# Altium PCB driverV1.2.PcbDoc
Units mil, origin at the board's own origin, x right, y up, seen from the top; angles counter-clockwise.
Board outline 6000 x 4000 mil, 2 copper layers (Top Layer, Bottom Layer); 172 components, 108 nets, 481 pads, 590 vias.
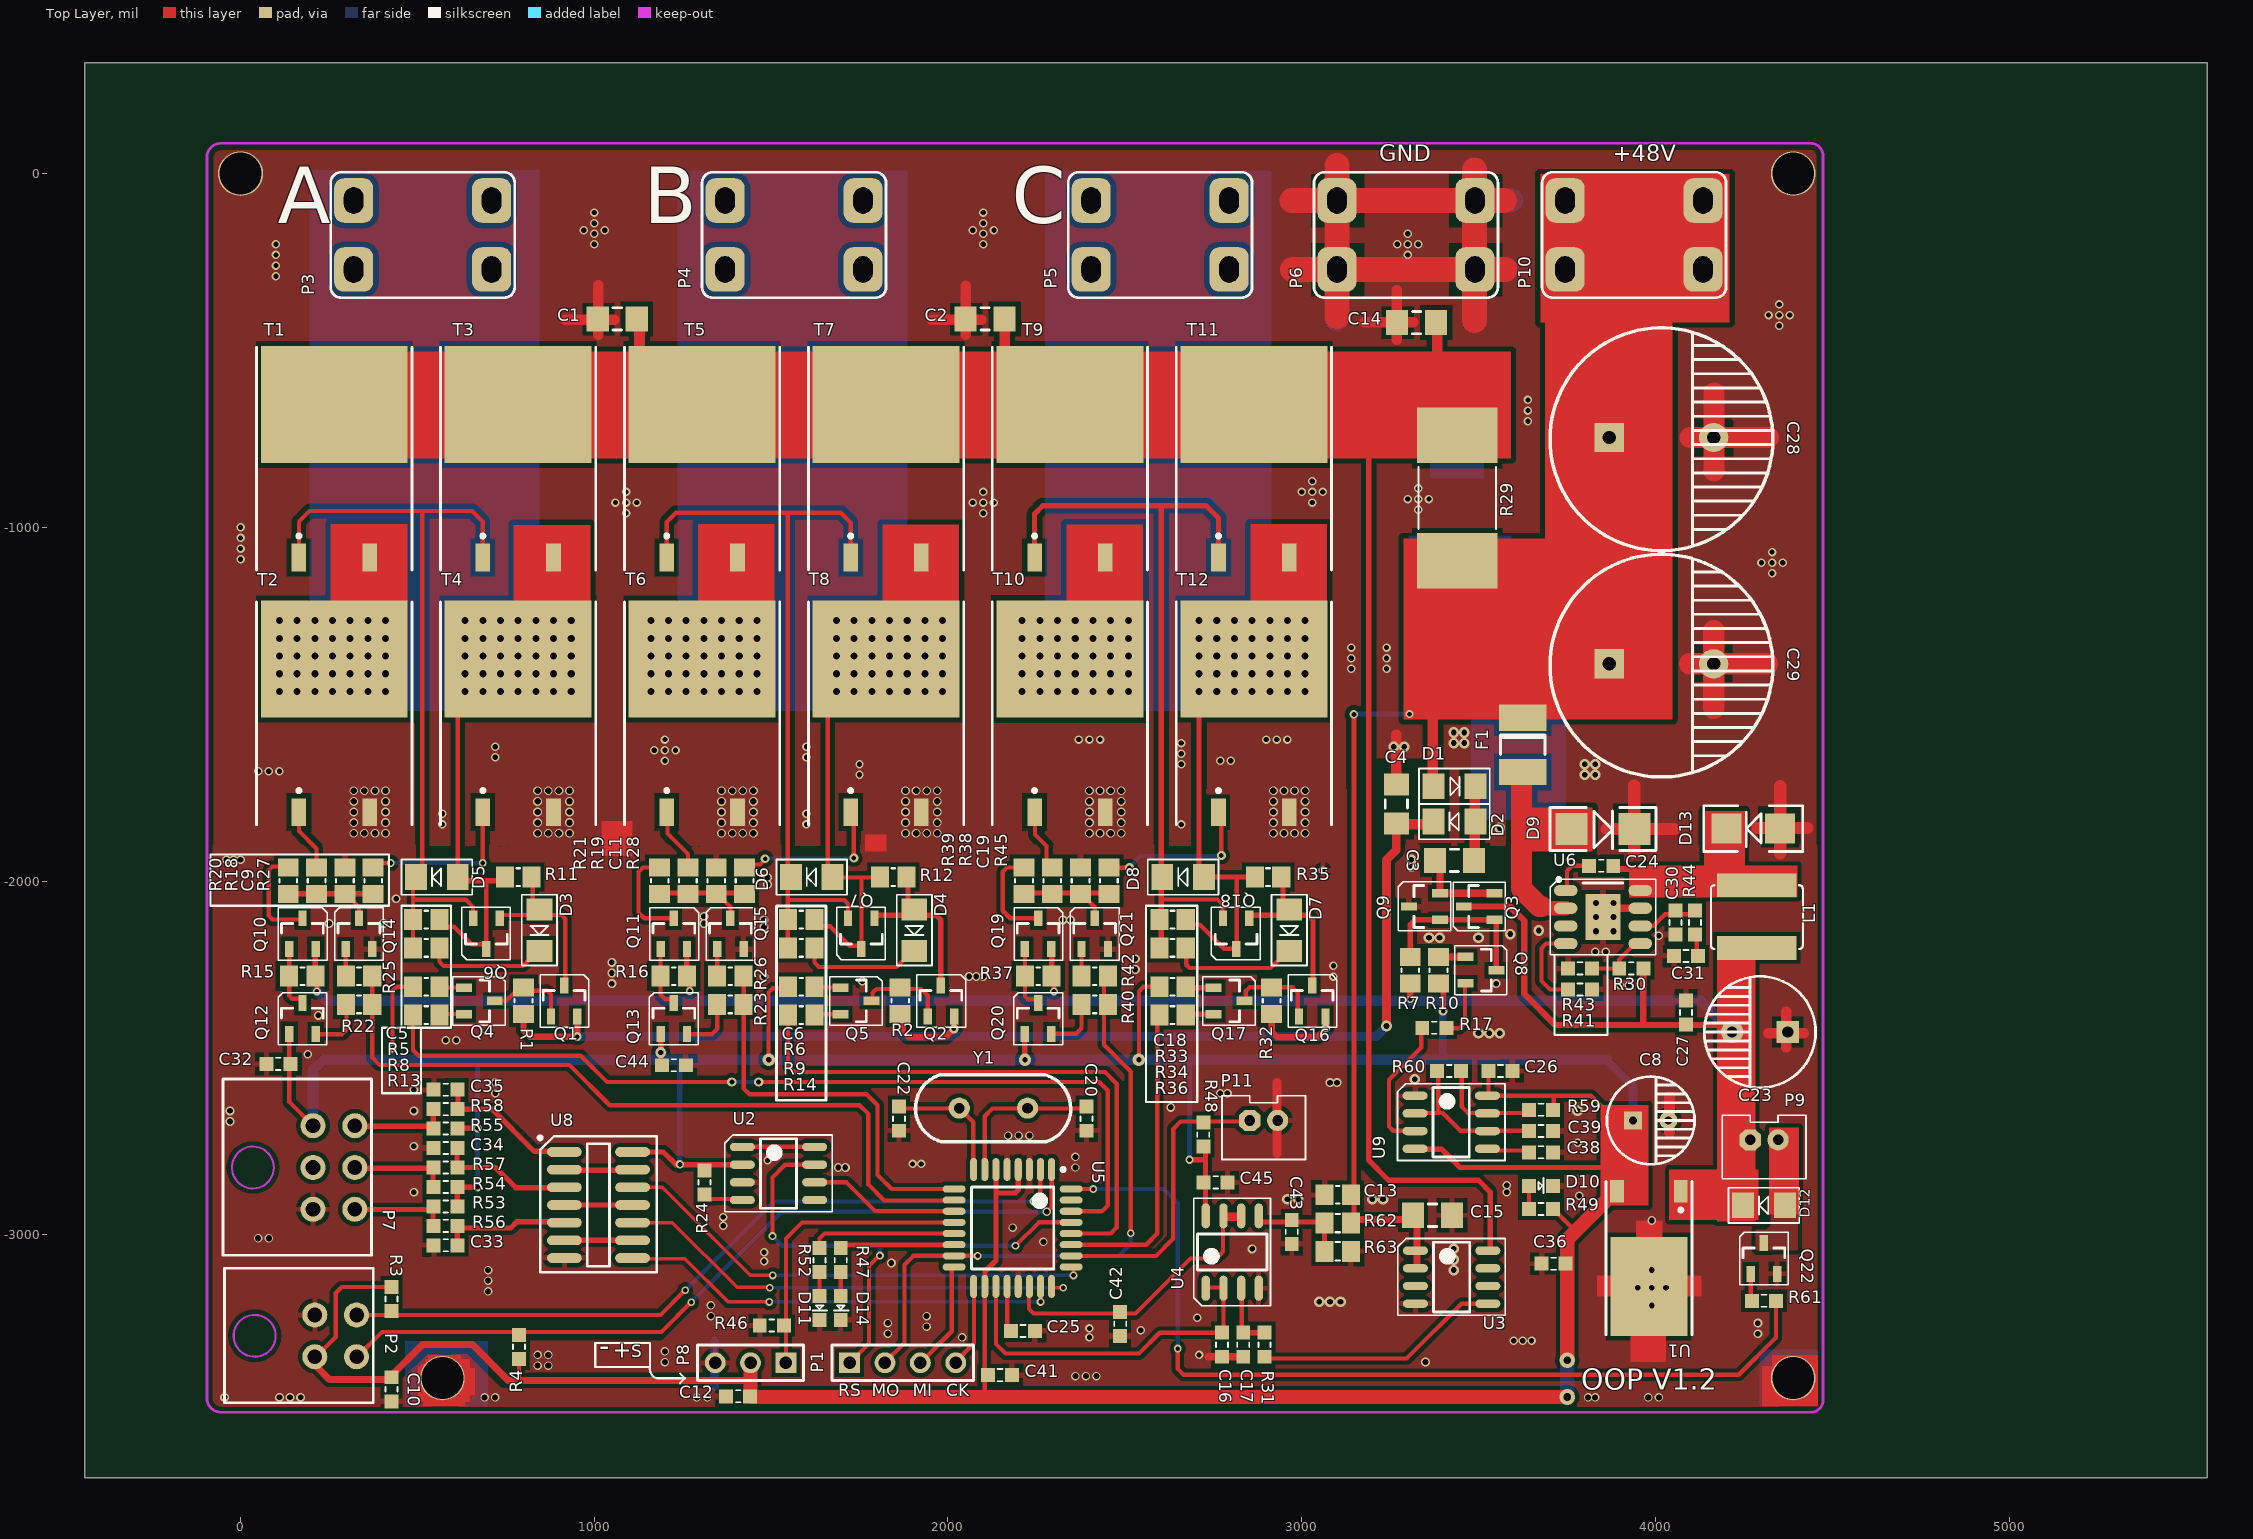
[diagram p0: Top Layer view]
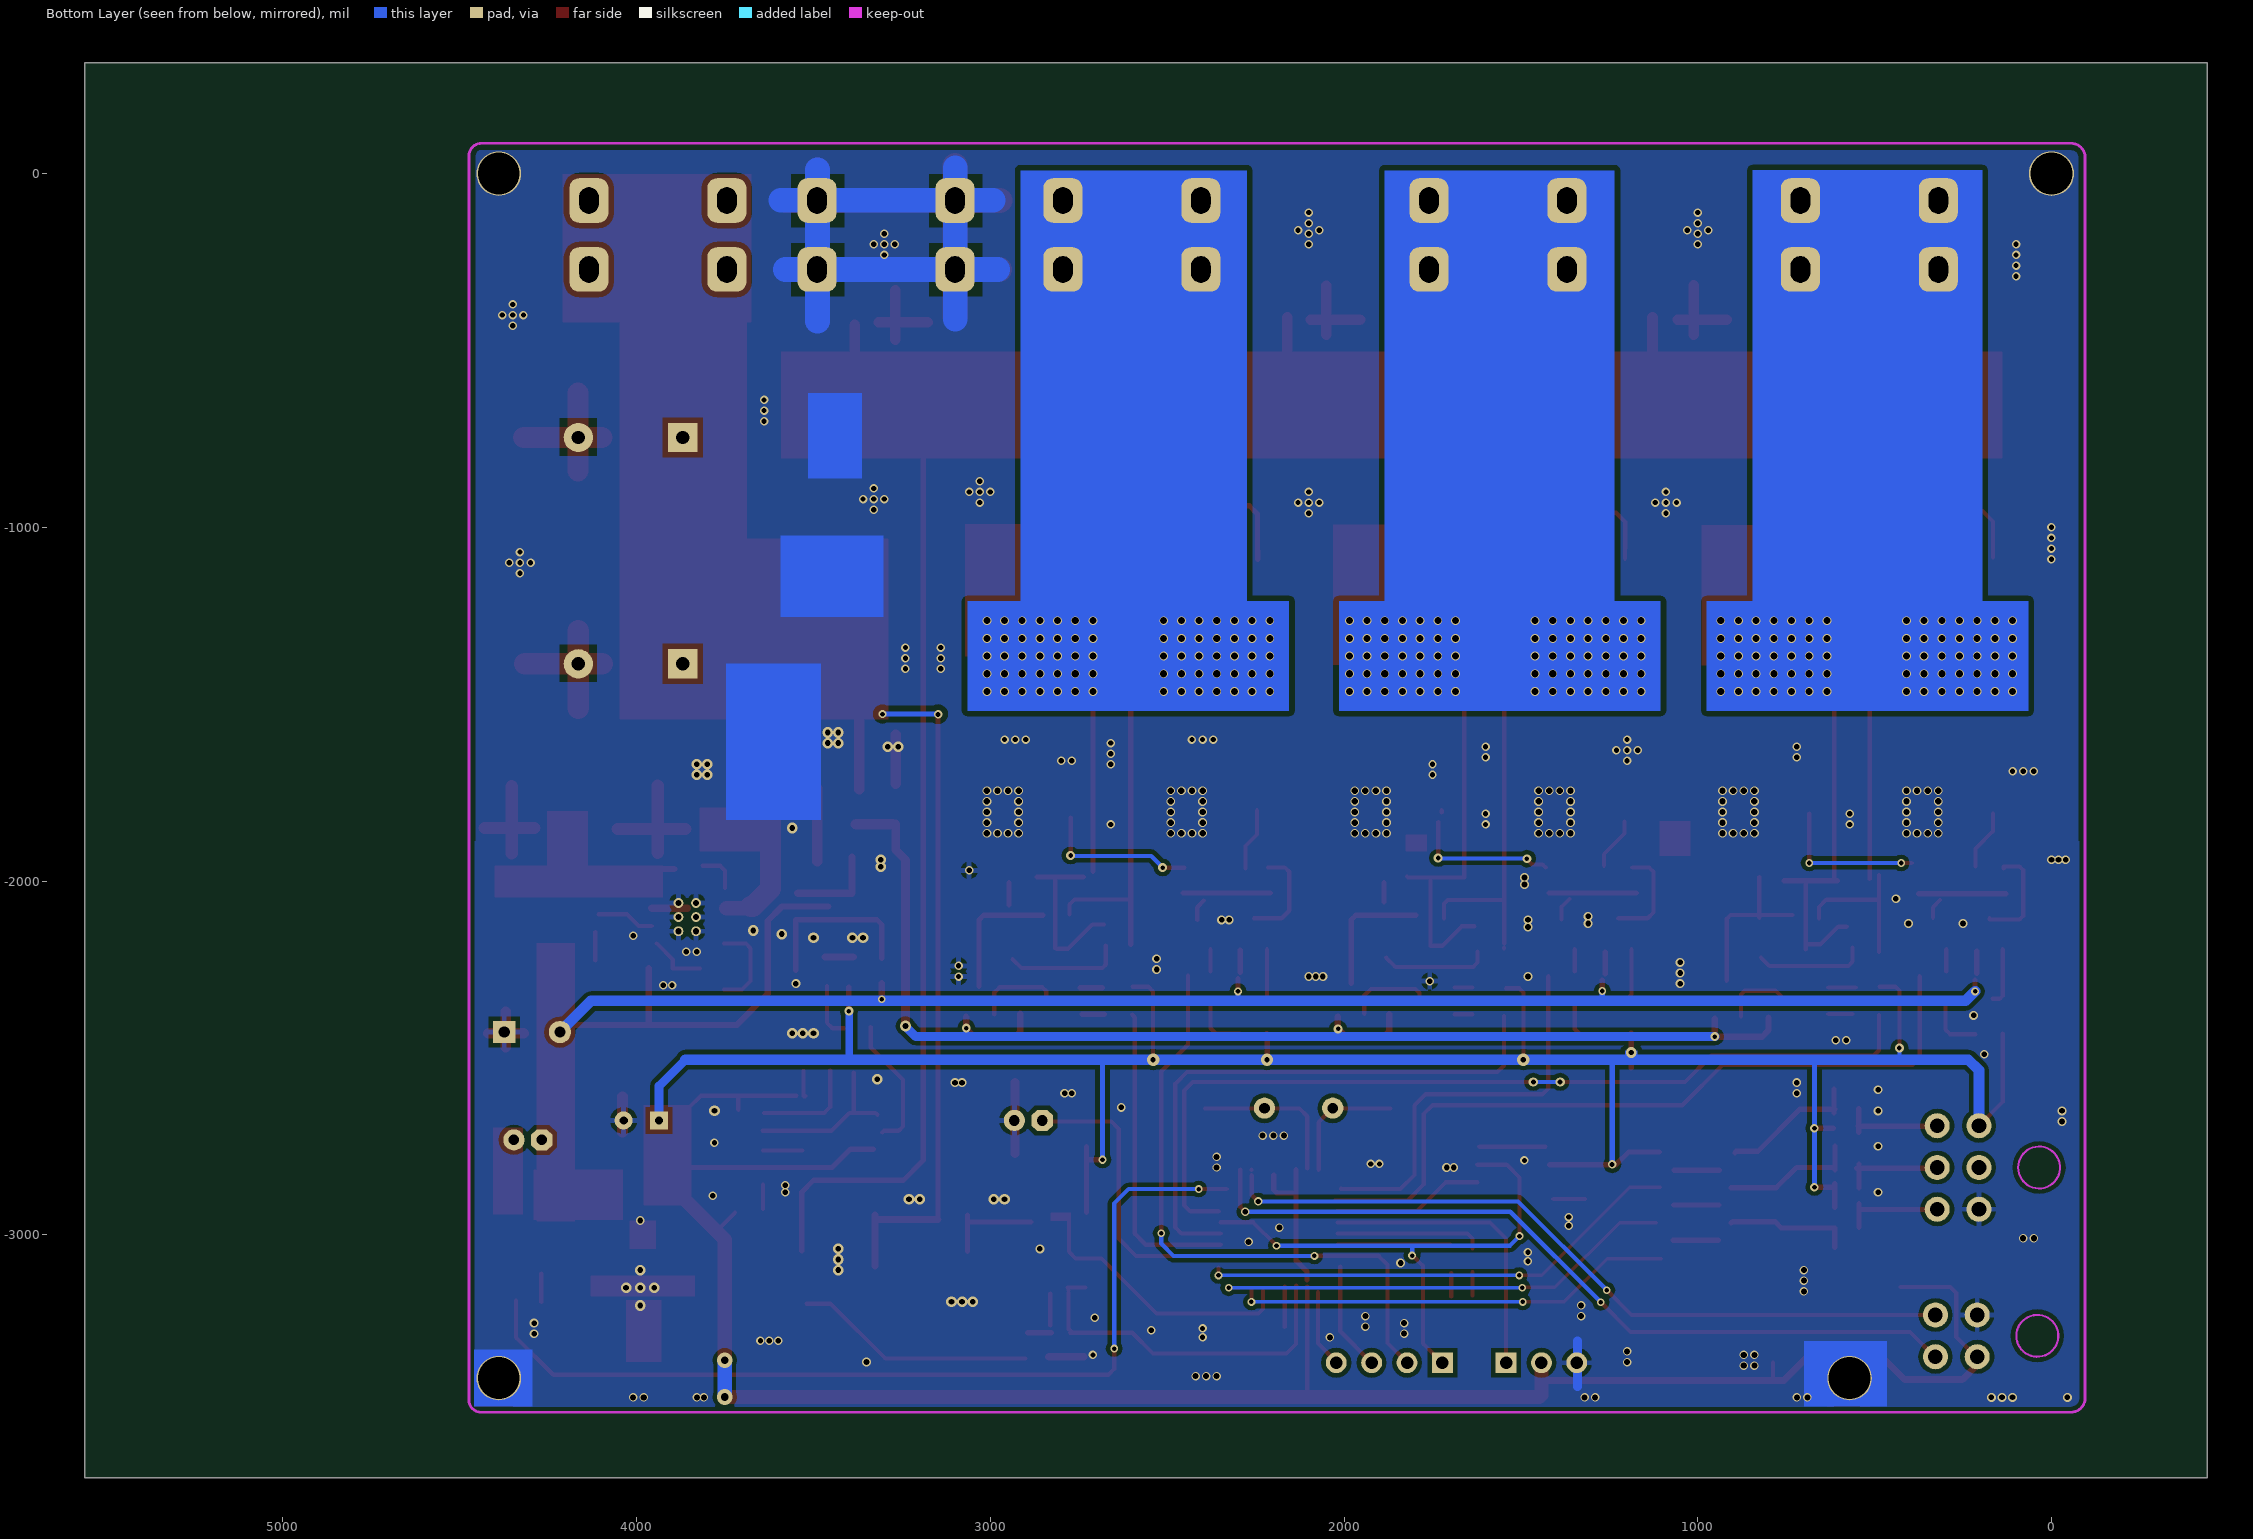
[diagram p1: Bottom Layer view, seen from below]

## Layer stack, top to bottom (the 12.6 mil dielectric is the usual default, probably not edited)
Top Solder: solder mask 0.4, Solder Resist, Dk 3.5
Top Layer: signal copper 1.4
Dielectric1: dielectric 12.6, FR-4, Dk 4.8
Bottom Layer: signal copper 1.4
Bottom Solder: solder mask 0.4, Solder Resist, Dk 3.5

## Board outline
-440,-3687 5560,-3687 5560,313 -440,313

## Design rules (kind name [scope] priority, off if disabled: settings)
Clearance [All] p1 off: gap=15
ComponentClearance [All] p1 off: gap=0 collisioncheckmode=3 verticalgap=0 showdistances=FALSE
FabricationTestPointUsage TestPointUsage [All] p1: valid=0 allowmultiple=FALSE
FabricationTestpoint Testpoint [All] p1: side=3 testpointundercomponent=TRUE minsize=40 maxsize=100 preferedsize=60 minholesize=0 maxholesize=40 preferedholesize=32 testpointgrid=1 allowsidetop=TRUE allowsidebottom=TRUE usegrid=TRUE gridtolerance=0.01
HoleSize [All] p1: absolutevalues=TRUE maxlimit=200 minlimit=1 maxpercent=80.000 minpercent=20.000
PolygonConnect [All] p1: connectstyle=Direct reliefconductorwidth=15 reliefentries=4 polygonreliefangle="90 Angle" airgapwidth=10
RoutingVias [All] p1: holewidth=13 width=22 viastyle="Through Hole" minholewidth=10 minwidth=15 maxholewidth=200 maxwidth=250
SolderMaskExpansion [All] p1: expansion=4
Width [All] p1: maxlimit=150 minlimit=10 preferedwidth=10 minimp=50.000000 maximp=50.000000 favimp=50.000000
26 further rules are at their usual default settings.

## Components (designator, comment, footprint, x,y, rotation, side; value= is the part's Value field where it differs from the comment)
C1 "Cap" 3216[1206] 1065,-411 r180 top
C2 "Cap" 3216[1206] 2105,-411 r180 top
C3 "Cap" 3216[1206] 3432,-1942 r180 top
C4 "Cap" 3216[1206] 3267.71,-1782 r90 top
C5 "Cap" R0805 525,-2109 r0 top
C6 "Cap" R0805 1585,-2109 r0 top
C8 "Cap Pol1" C6.3*12 4037,-2677 r180 top
C9 "Cap" R0805 295,-1999 r270 top
C10 "Cap" 0603 427,-3437 r90 top
C11 "Cap" R0805 1345,-1999 r270 top
C12 "Cap" 0603 1407,-3457 r0 top
C13 "Cap" R0805 3102,-2887 r0 top
C14 "Cap" 3216[1206] 3325,-421 r180 top
C15 "Cap" 3216[1206] 3370,-2945 r0 top
C16 "Cap" 0603 2775,-3311 r90 top
C17 "Cap" 0603 2835,-3311 r90 top
C18 "Cap" R0805 2635,-2109 r0 top
C19 "Cap" R0805 2375,-1999 r270 top
C20 "Cap" 0603 2392,-2672 r270 top
C22 "Cap" 0603 1862,-2672 r270 top
C23 "Cap Pol3" C8x4 4217,-2427 r0 top
C24 "Cap" 0603 3847,-1957 r180 top
C25 "Cap" 0603 2212,-3272 r0 top
C26 "Cap" 0603 3562,-2537 r180 top
C27 "Cap" 0603 4087,-2372 r90 top
C28 "Cap Pol1" C16-7.5 4165,-1386 r180 top
C29 "Cap Pol1" C16-7.5 4165,-746 r180 top
C30 "Cap" 0603 4057,-2117 r270 top
C31 "Cap" 0603 4087,-2212 r0 top
C32 "Cap" 0603 107,-2517 r180 top
C33 "Cap" 0603 580,-3030 r0 top
C34 "Cap" 0603 580,-2755 r0 top
C35 "Cap" 0603 580,-2590 r0 top
C36 "Cap" 0603 3712,-3082 r180 top
C38 "Cap" 0603 3677,-2767 r0 top
C39 "Cap" 0603 3677,-2707 r0 top
C41 "Cap" 0603 2147,-3397 r180 top
C42 "Cap" 0603 2487,-3252 r90 top
C43 "Cap" 0603 2972,-2992 r90 top
C44 "Cap" 0603 1225,-2521 r180 top
C45 "Cap" 0603 2757,-2852 r180 top
D1 "Diode" LL34 3432,-1732 r0 top
D2 "Diode" LL34 3432,-1832 r180 top
D3 "Diode" LL34 845,-2139 r270 top
D4 "Diode" LL34 1905,-2139 r270 top
D5 "Zener diode" LL34 555,-1989 r180 top
D6 "Zener diode" LL34 1615,-1989 r180 top
D7 "Diode" LL34 2965,-2139 r270 top
D8 "Zener diode" LL34 2665,-1989 r180 top
D9 "SMBJ45CA" SMB 3852,-1852 r0 top
D10 "WORK" 0603-LED 3677,-2862 r0 top
D11 "FALT" 0603-LED 1637,-3207 r270 top
D12 "Diode" LL34 4307,-2917 r180 top
D13 "SS54" SMA 4277,-1852 r180 top
D14 "FALT" 0603-LED 1697,-3207 r270 top
F1 "Fuse Thermal" 1812 3625,-1615 r270 top
L1 "Inductor" L-6045 4287,-2012 r270 top
P1 "PROG" HDR1X4 1722,-3362 r0 top
P2 "ENC" 5557-4-SMALL 210,-3345 r270 top
P3 "M5" M4 710,-76 r180 top
P4 "M5" M4 1760,-76 r180 top
P5 "M5" M4 2795,-76 r180 top
P6 "M5" M4 3490,-76 r180 top
P7 "HALL" 5557-6-small 205,-2810 r270 top
P8 "S1" HDR1X3 1542,-3362 r180 top
P9 "FAN" PH2.0-2P 4347,-2732 r0 top
P10 "M5" M4 4135,-76 r180 top
P11 "RT" PH2.0-2P 2932,-2677 r0 top
Q1 "PNP" SOT-23-PNP 915,-2339 r0 top
Q2 "PNP" SOT-23-PNP 1980,-2339 r0 top
Q3 "NPN" SOT-23-NPN 3502,-2072 r90 top
Q4 "NPN" SOT-23-NPN 675,-2339 r270 top
Q5 "NPN" SOT-23-NPN 1740,-2339 r270 top
Q6 "PNP" SOT-23-PNP 695,-2149 r180 top
Q7 "PNP" SOT-23-PNP 1755,-2149 r180 top
Q8 "NPN" SOT-23-NPN 3507,-2252 r270 top
Q9 "PNP" SOT-23-PNP 3347,-2072 r90 top
Q10 "PNP" SOT-23-PNP 175,-2149 r0 top
Q11 "PNP" SOT-23-PNP 1225,-2149 r0 top
Q12 "NPN" SOT-23-NPN 175,-2389 r0 top
Q13 "NPN" SOT-23-NPN 1225,-2389 r0 top
Q14 "NPN" SOT-23-NPN 335,-2149 r0 top
Q15 "NPN" SOT-23-NPN 1385,-2149 r0 top
Q16 "PNP" SOT-23-PNP 3030,-2339 r0 top
Q17 "NPN" SOT-23-NPN 2795,-2339 r270 top
Q18 "PNP" SOT-23-PNP 2815,-2149 r180 top
Q19 "PNP" SOT-23-PNP 2255,-2149 r0 top
Q20 "NPN" SOT-23-NPN 2255,-2389 r0 top
Q21 "NPN" SOT-23-NPN 2415,-2149 r0 top
Q22 "NPN" SOT-23-NPN 4307,-3067 r0 top
R1 "Res1" R0805 800,-2339 r270 top
R2 "Res1" R0805 1865,-2339 r270 top
R3 "Res1" 0603 427,-3182 r270 top
R4 "Res1" 0603 787,-3317 r90 top
R5 "Res1" R0805 525,-2189 r180 top
R6 "Res1" R0805 1585,-2189 r180 top
R7 "Res1" R0805 3307,-2252 r270 top
R8 "Res1" R0805 525,-2299 r180 top
R9 "Res1" R0805 1585,-2299 r180 top
R10 "Res1" R0805 3387,-2252 r270 top
R11 "Res1" R0805 785,-1989 r0 top
R12 "Res1" R0805 1845,-1989 r0 top
R13 "Res1" R0805 525,-2379 r0 top
R14 "Res1" R0805 1585,-2379 r0 top
R15 "Res1" R0805 175,-2269 r180 top
R16 "Res1" R0805 1225,-2269 r180 top
R17 "Res1" 0603 3375,-2415 r0 top
R18 "Res1" R0805 215,-1999 r270 top
R19 "Res1" R0805 1265,-1999 r270 top
R20 "Res1" R0805 135,-1999 r270 top
R21 "Res1" R0805 1185,-1999 r270 top
R22 "Res1" R0805 335,-2349 r180 top
R23 "Res1" R0805 1385,-2349 r180 top
R24 "Res1" 0603 1312,-2852 r90 top
R25 "Res1" R0805 335,-2269 r0 top
R26 "Res1" R0805 1385,-2269 r0 top
R27 "Res1" R0805 375,-1999 r270 top
R28 "Res1" R0805 1425,-1999 r270 top
R29 "" 3920 3440,-740 r270 top
R30 "Res1" 0603 3932,-2247 r0 top
R31 "Res1" 0603 2895,-3311 r270 top
R32 "Res1" R0805 2915,-2339 r270 top
R33 "Res1" R0805 2635,-2189 r180 top
R34 "Res1" R0805 2635,-2299 r180 top
R35 "Res1" R0805 2905,-1989 r0 top
R36 "Res1" R0805 2635,-2379 r0 top
R37 "Res1" R0805 2255,-2269 r180 top
R38 "Res1" R0805 2295,-1999 r270 top
R39 "Res1" R0805 2215,-1999 r270 top
R40 "Res1" R0805 2415,-2349 r180 top
R41 "Res1" 0603 3787,-2307 r0 top
R42 "Res1" R0805 2415,-2269 r0 top
R43 "Res1" 0603 3787,-2247 r0 top
R44 "Res1" 0603 4112,-2117 r270 top
R45 "Res1" R0805 2455,-1999 r270 top
R46 "Res1" 0603 1502,-3257 r180 top
R47 "Res1" 0603 1697,-3072 r90 top
R48 "Res1" 0603 2722,-2717 r270 top
R49 "Res1" 0603 3677,-2927 r0 top
R52 "Res1" 0603 1637,-3072 r90 top
R53 "Res Semi" 0603 580,-2920 r0 top
R54 "Res Semi" 0603 580,-2865 r0 top
R55 "Res Semi" 0603 580,-2700 r0 top
R56 "Res Semi" 0603 580,-2975 r180 top
R57 "Res Semi" 0603 580,-2810 r180 top
R58 "Res Semi" 0603 580,-2645 r180 top
R59 "Res1" 0603 3677,-2647 r0 top
R60 "Res1" 0603 3417,-2537 r0 top
R61 "Res Semi" 0603 4307,-3187 r0 top
R62 "Res1" 0805 3102,-2967 r0 top
R63 "Res1" 0805 3102,-3047 r0 top
T1 "CSD19536" D2PAK 265,-869 r0 top
T2 "CSD19536" D2PAK 265,-1589 r0 top
T3 "CSD19536" D2PAK 785,-869 r0 top
T4 "CSD19536" D2PAK 785,-1589 r0 top
T5 "CSD19536" D2PAK 1305,-869 r0 top
T6 "CSD19536" D2PAK 1305,-1589 r0 top
T7 "CSD19536" D2PAK 1825,-869 r0 top
T8 "CSD19536" D2PAK 1825,-1589 r0 top
T9 "CSD19536" D2PAK 2345,-869 r0 top
T10 "CSD19536" D2PAK 2345,-1589 r0 top
T11 "CSD19536" D2PAK 2865,-869 r0 top
T12 "CSD19536" D2PAK 2865,-1589 r0 top
U1 "L7805ACD2T-TR" TO-252 3962,-3097 r180 top
U2 "MAX706RCSA" SOIC8 1522,-2827 r0 top
U3 "MAX4080T" SOIC8 3425,-3120 r0 top
U4 "LM358D" SOIC8 2804,-3048 r90 top
U5 "ATmega8-16AC" 32A_N 2183,-2981 r270 top
U6 "TPS54360" SOP8-POW 3852,-2102 r0 top
U8 "MC74HC14AD" 751A 1012,-2916 r0 top
U9 "NE555D" SOIC8 3424,-2682 r0 top
Y1 "XTAL(8M)" 49SD 2032,-2642 r0 top

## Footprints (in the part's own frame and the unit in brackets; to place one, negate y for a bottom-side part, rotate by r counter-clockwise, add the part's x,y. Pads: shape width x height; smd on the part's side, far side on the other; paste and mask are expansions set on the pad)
32A_N [mm] "32-Pin Thin Quad Flat Pack 0.8 mm Pitch, IPC Medium Density"
  oval 1.65x0.508 smd: 1(-4.2,2.8) 2(-4.2,2) 3(-4.2,1.2) 4(-4.2,0.4) 5(-4.2,-0.4) 6(-4.2,-1.2) 7(-4.2,-2) 8(-4.2,-2.8) 17(4.2,-2.8) 18(4.2,-2) 19(4.2,-1.2) 20(4.2,-0.4) 21(4.2,0.4) 22(4.2,1.2) 23(4.2,2) 24(4.2,2.8)
  oval 0.508x1.65 smd: 9(-2.8,-4.2) 10(-2,-4.2) 11(-1.2,-4.2) 12(-0.4,-4.2) 13(0.4,-4.2) 14(1.2,-4.2) 15(2,-4.2) 16(2.8,-4.2) 25(2.8,4.2) 26(2,4.2) 27(1.2,4.2) 28(0.4,4.2) 29(-0.4,4.2) 30(-1.2,4.2) 31(-2,4.2) 32(-2.8,4.2)
  silkscreen extent -4.32,-2.95 2.95,3.75, body extent -3.5,-3.5 3.5,3.5, height 1.2
49SD [mil]
  round 60 hole 30: 1(0,0) 2(193,0)
  silkscreen extent -124,-95 315,94
0603 [mm]
  rect 1x1 smd: 1(-0.864,0) 2(0.864,0)
  silkscreen extent -0.18,-0.43 0.18,0.43
0603-LED [mm]
  rect 1x1 smd: 1(-0.864,0) 2(0.864,0)
  silkscreen extent -0.18,-0.51 0.18,0.56
751A [mm]
  oval 2.5x0.7 smd: 1(-2.45,3.81) 2(-2.45,2.54) 3(-2.45,1.27) 4(-2.45,0) 5(-2.45,-1.27) 6(-2.45,-2.54) 7(-2.45,-3.81) 8(2.45,-3.81) 9(2.45,-2.54) 10(2.45,-1.27) 11(2.45,0) 12(2.45,1.27) 13(2.45,2.54) 14(2.45,3.81)
  silkscreen extent -4.31,-4.83 4.19,4.95, body extent -2,-4.38 2,4.38, height 1.75
0805 [mm]
  rect 1.3x1.5 smd: 1(-0.95,0) 2(0.95,0)
  silkscreen extent -0.15,-0.66 0.15,0.66
1812 [mm] "Chip Capacitor; Body 4.5 x 3.2 mm (LxW typ)"
  rect 1.9x3.4 smd: 1(-1.95,0) 2(1.95,0)
  silkscreen extent -0.7,-1.6 0.7,1.6
3216[1206] [mm] "Chip Resistor; Body 3.2 x 1.6 mm (LxW typ)"
  rect 1.6x1.8 smd: 1(-1.4,0) 2(1.4,0)
  silkscreen extent -0.3,-0.8 0.3,0.8
3920 [mm]
  rect 4x5.8 smd: 1(0,0) 2(9,0)
  silkscreen extent 2.29,-2.79 6.73,2.79
5557-4-SMALL [mm]
  round 1.8 hole 1.05: 1(0,0) 2(-3,0) 3(-3,3) 4(0,3)
  Keep-Out Layer circle w0.152: c-1.5,-4.32 r1.505
  silkscreen extent -6.35,-6.48 3.3,4.19
5557-6-small [mm]
  round 1.8 hole 1.05: 1(3,0) 2(0,0) 3(-3,0) 4(-3,3) 5(0,3) 6(3,3)
  Keep-Out Layer circle w0.152: c0,-4.32 r1.505
  silkscreen extent -6.35,-6.48 6.3,4.19
C6.3*12 [mm]
  rect 1.3x1.3 hole 0.6: 1(2.54,0)
  round 1.3 hole 0.6: 2(0,0)
  silkscreen extent -1.88,-3.15 4.42,3.15
C8x4 [mm]
  round 1.6 hole 0.8: 1(0,0)
  rect 1.6x1.6 hole 0.8: 2(4,0)
  silkscreen extent -2,-4 6,4
C16-7.5 [mm]
  rect 2.1x2.1 hole 0.95: 1(7.5,0)
  round 2.1 hole 0.95: 2(0,0)
  silkscreen extent -4.25,-7.87 11.75,8.12
D2PAK [mm] "D2-PAK/TO-263-AB; 3 Leads (1 Cropped); Body 15.5 (inc. leads) x 10.5 mm (LxW max)"
  rect 1.05x2 smd: 1(-2.54,-5.5) 3(2.54,-5.5)
  rect 10.55x8.4 smd: 2(0,5.5)
  silkscreen extent -5.58,-6.4 5.58,9.6
HDR1X3 [mm] "Connector; Header; 3 Position"
  rect 1.5x1.5 hole 0.9: 1(0,0)
  round 1.5 hole 0.9: 2(2.54,0) 3(5.08,0)
  silkscreen extent -1.27,-1.27 6.35,1.27
HDR1X4 [mm] "Connector; Header; 4 Position"
  rect 1.5x1.5 hole 0.9: 1(0,0)
  round 1.5 hole 0.9: 2(2.54,0) 3(5.08,0) 4(7.62,0)
  silkscreen extent -1.27,-1.27 8.89,1.27
L-6045 [mm]
  rect 1.7x5.7 smd: 1(0,0) 2(4.5,0)
  silkscreen extent 0,-3.3 4.57,3.3
LL34 [mm] "MELF Diode, 2-Leads, Body 3.3x1.6mm, IPC Medium Density"
  rect 1.575x1.85 smd: 1(-1.5,0) 2(1.5,0)
  silkscreen extent -2.54,-1.27 2.54,1.27, body extent -1.65,-0.82 1.65,0.82, height 1.65
M4 [mm]
  rrect50% 2.8x3.2 hole 1.4 slot 1.9 at 90 deg: 1(0,4.953) 1(0,0) 1(9.906,0) 1(9.906,4.953)
  silkscreen extent -1.65,-2.03 11.56,6.99
PH2.0-2P [mil]
  oct 60x60 hole 30: 1(-78.74,0)
  round 60 hole 30: 2(0,0)
  silkscreen extent -157,-110 79,70
R0805 [mm] "Chip Resistor, 2-Leads, Body 2.0x1.3mm, IPC Medium Density"
  rect 1.298x1.501 smd: 1(-0.95,0) 2(0.95,0)
  silkscreen extent -0.13,-0.64 0.13,0.64
SMA [mm] "Molded Diode, 2-Leads, Body 4.3x2.7mm, IPC Medium Density"
  rect 2.15x2.15 smd: 1(-1.93,0) 2(1.93,0)
  silkscreen extent -3.56,-1.65 3.56,1.65, body extent -2.28,-1.42 2.29,1.42, height 2.95
SMB [mm]
  rect 2.3x2.3 smd: 1(-2.25,-0.025) 2(2.25,-0.025)
  silkscreen extent -3.8,-1.58 3.81,1.52
SOIC8 [mm]
  oval 1.8x0.6 smd: 1(-2.625,1.905) 2(-2.625,0.635) 3(-2.625,-0.635) 4(-2.625,-1.905) 5(2.575,-1.905) 6(2.575,-0.635) 7(2.575,0.635) 8(2.575,1.905)
  silkscreen extent -3.89,-2.74 3.84,2.77, body extent -2.03,-2.5 1.97,2.5, height 1.76
SOP8-POW [mm]
  round 0.715 hole 0.45: 0(-0.508,-1.016) 0(-0.508,0) 0(-0.508,1.016) 0(0.762,-1.016) 0(0.762,0) 0(0.762,1.016)
  rect 2.54x3.302 smd: 0(0,0)
  oval 1.7x0.8 smd: 1(-2.675,1.905) 2(-2.675,0.635) 3(-2.675,-0.635) 4(-2.675,-1.905) 5(2.675,-1.905) 6(2.675,-0.635) 7(2.675,0.635) 8(2.675,1.905)
  silkscreen extent -3.78,-2.7 3.77,2.82
SOT-23-NPN [mm]
  rect 0.6x1.143 smd: 1(0.95,-1.108) 2(-0.95,-1.108) 3(0,1.108)
  silkscreen extent -1.75,-1.89 1.75,1.87, body extent -1.5,-0.66 1.5,0.74, height 1.1
SOT-23-PNP [mm]
  rect 0.6x1.143 smd: 1(0.95,-1.108) 2(-0.95,-1.108) 3(0,1.108)
  silkscreen extent -1.73,-1.89 1.78,1.87, body extent -1.5,-0.66 1.5,0.74, height 1.1
TO-252 [mm]
  rect 1x1.6 smd: 1(-2.793,-5.584) 3(1.777,-5.584)
  rect 5.5x7.1 smd: 4(-0.508,1.266)
  silkscreen extent -3.59,-6.28 2.58,4.72

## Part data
C1 C2 C3 C4 C5 C6 C9 C10 C11 C12 C13 C14 C15 C16 C17 C18 C19 C20 C22 C24 C25 C26 C27 C30 C31 C32 C33 C34 C35 C36 C38 C39 C41 C42 C43 C44 C45: "Capacitor"
C8 C28 C29: "Polarized Capacitor (Radial)"
C23: library part Cap, "Capacitor"
D1 D2 D3 D4 D7 D12: library part "Diode 1N5408", "3 Amp Medium Power Silicon Rectifier Diode"
D5 D6 D8: library part "D Zener", "Zener Diode"
D9: library part NUP2105L
D10 D11 D14: library part LED2, "Typical RED, GREEN, YELLOW, AMBER GaAs LED"
D13: library part "Diode BAS16", "Silicon Switching Diode for High-Speed Switching"
F1: "Thermal Fuse"
L1: library part B82793S0513N201
P1 P7: library part "Header 5", "Header, 5-Pin"
P2: library part "Header 4", "Header, 4-Pin"
P6 P9 P11: library part "Header 2", "Header, 2-Pin"
P8: library part "Header 3", "Header, 3-Pin"
Q1 Q2 Q6 Q7 Q9 Q10 Q11 Q16 Q18 Q19: library part 2N5401, "PNP General Purpose Amplifier"
Q3 Q4 Q5 Q8 Q12 Q13 Q14 Q15 Q17 Q20 Q21 Q22: library part 2N5551, "NPN General Purpose Amplifier"
R1 R2 R3 R4 R5 R6 R7 R8 R9 R10 R11 R12 R13 R14 R15 R16 R17 R18 R19 R20 R21 R22 R23 R24 R25 R26 R27 R28 R30 R31 R32 R33 R34 R35 R36 R37 R38 R39 R40 R42 R45 R46 R47 R48 R49 R52 R59 R60 R62 R63: "Resistor"
R29: library part Res1, "Resistor"
R41 R43 R44: library part "Res Semi", "Semiconductor Resistor"
R53 R54 R55 R56 R57 R58 R61: "Semiconductor Resistor"
T1 T2 T3 T4 T5 T6 T7 T8 T9 T10 T11 T12: library part IRF644S, "HEXFET N-Channel Power MOSFET"
U1: library part MC78M05ACDTRK, "Three-Terminal Medium Current Positive Voltage Regulator"
U2: "+3V Voltage Monitoring, Low-Cost, µP Supervisory Circuit"
U3: library part MAX4080
U4: "Dual Low-Power Operational Amplifier"
U5: "8-Bit AVR Microcontroller with 8K Bytes of In-System Programmable Flash Memory"
U6: library part TJA1040
U8: "Hex Schmitt-Trigger Inverter"
U9: "Precision Timer"
Y1: library part XTAL, "Crystal Oscillator"

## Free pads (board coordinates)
  round 125.98 hole 118.11: 0(570.87,-3405.51) 1(4389.76,-3405.51) 2(4389.76,0)
  oval 127.17x125.98 hole 118.11: 3(0,0)

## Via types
v1: diameter 25, hole 20, Top Layer to Bottom Layer, 210 vias
v2: diameter 24, hole 15, Top Layer to Bottom Layer, 121 vias
v3: diameter 25, hole 18, Top Layer to Bottom Layer, 84 vias
v4: diameter 25, hole 16, Top Layer to Bottom Layer, 57 vias
v5: diameter 30, hole 16, Top Layer to Bottom Layer, 38 vias
v6: diameter 24, hole 17, Top Layer to Bottom Layer, 36 vias
v7: diameter 22, hole 13, Top Layer to Bottom Layer, 21 vias
v8: diameter 25, hole 13, Top Layer to Bottom Layer, 9 vias
v9: diameter 24, hole 13, Top Layer to Bottom Layer, 3 vias
v10: diameter 35, hole 15, Top Layer to Bottom Layer, 3 vias
v11: diameter 26, hole 14, Top Layer to Bottom Layer, 2 vias
v12: diameter 45, hole 22, Top Layer to Bottom Layer, 2 vias
v13: diameter 25, hole 14, Top Layer to Bottom Layer, 1 vias
v14: diameter 23, hole 13, Top Layer to Bottom Layer, 1 vias
v15: diameter 30, hole 17, Top Layer to Bottom Layer, 1 vias
v16: diameter 30, hole 15, Top Layer to Bottom Layer, 1 vias

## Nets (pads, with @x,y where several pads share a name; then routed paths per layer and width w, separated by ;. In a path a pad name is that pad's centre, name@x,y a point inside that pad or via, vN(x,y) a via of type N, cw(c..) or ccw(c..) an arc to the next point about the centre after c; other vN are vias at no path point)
+5V: C8.1 C10.2 C12.2 C26.2 C32.1 C36.1 C41.2 C44.2 C45.2 P2.1 P7.3 P8.2 Q12.2 Q13.2 Q20.2 R3.1 R4.1 R8.2 R9.2 R10.2 R24.2 R34.2 R48.2 R49.2 R53.2 R54.2 R55.2 R59.2 U1.3 U2.2 U4.8 U5.4 U5.6 U5.18 U8.14 U9.4 U9.8 | length 13691
  Top Layer w12: Q12.2@137.99,-2432.64 Q12.2@138,-2432 ; Q12.2@138,-2431 138,-2624.89 P7.3 ; P2.1@213,-3345 269,-3289 269,-3165 286,-3148 R3.1 ; v8(430,-2472) 430,-2310 441,-2299 R8.2@486,-2299 ; 787,-3412 R4.1@787,-3362 ; v10(1493,-2505) 1493,-2315 1505,-2303 R9.2@1542,-2303 ; 2104.26,-3459 U5.18 ; v10(2540,-2505) 2540,-2312 2553,-2299 R34.2 ; U9.8@3528,-2606 C26.2 ; U9.8@3549,-2607 3818,-2607 3853,-2642 ; R59.2@3713,-2647 3713,-2607 ; R49.2@3722,-2938 3770.08,-2986.08
  Top Layer w15: R53.2@613,-2922 R54.2@613,-2855 ; R54.2@615,-2866 v9(670,-2866) ; R55.2@616,-2699 v9(670,-2699) ; U8.14 1195,-2766 1231,-2802 U2.2 ; C44.2@1188,-2528 Q13.2@1188,-2430 ; U5.18@2105,-3128 2105,-3104 2135.76,-3073.24 U5.6 ; 2140.26,-2882 2190,-2882 2199,-2873 U5.4@2199,-2831 ; v10@2217.6,-2505 Q20.2@2217.6,-2436 ; Q20.2@2218.92,-2432.7 Q20.2@2219,-2431 ; v9(2683,-2788) 2722,-2788 ; U4.8@2728,-2937 R48.2@2728,-2751 ; U9.4@3331,-2758 3395.73,-2758 3447.73,-2810 3875,-2810 ; v8@3400,-2367 R10.2@3400,-2300 ; U9.8@3524.36,-2608 U9.8@3526,-2608
  Top Layer w20: P2.1 213,-3345 P2.1@213,-3337 ; P2.1@216,-3350 216,-3374 251,-3409 416,-3409 515,-3310 655,-3310 757,-3412 1447.51,-3412
  Top Layer w40: P8.2 1442,-3453 1448,-3459 v12(3751,-3459) ; v12(3751,-3355) 3751,-3014 U1.3@3877,-2888
  Bottom Layer w12: 430,-2505 v8(430,-2472)
  Bottom Layer w15: v9(670,-2866) 670,-2515 ; v13(1242,-2801) 1242,-2518 ; v9(2683,-2788) 2683,-2517
  Bottom Layer w20: 3399,-2505 v8@3399,-2368
  Bottom Layer w25: 3862,-2505 3937,-2580 C8.1
  Bottom Layer w30: P7.3 205,-2535 235,-2505 3862,-2505
  Bottom Layer w40: v12(3751,-3459) v12(3751,-3355)
  other v8: 3400,-2368
  other v10: 2218,-2505
  other v16: 1188,-2485
+12V: C23.1 C27.1 D12.2 L1.2 P9.1 Q3.3 Q10.1 Q11.1 Q19.1 R7.2 R15.1 R16.1 R30.2 R37.1 U1.1 | length 5604.5
  Top Layer w15: R15.1@211.6,-2261.04 Q10.1@211.6,-2198.64 ; v7@216,-2313 R15.1@216,-2281 ; R16.1@1261.6,-2263.04 Q11.1@1261.6,-2200.64 ; v7(1270,-2311) R16.1@1270,-2280 ; R37.1@2293.4,-2258.36 Q19.1@2293.4,-2195.96 ; v7(2300,-2312) R37.1@2300,-2276.6
  Top Layer w18: v7(3307,-2334) R7.2 ; Q3.3 3589,-2072 3629,-2112 3629,-2319 3717,-2407 C23.1@4206,-2407 ; 3966,-2405 R30.2
  Bottom Layer w15: 1270,-2341 v7(1270,-2311) ; 2300,-2342 v7(2300,-2312)
  Bottom Layer w30: v7(216,-2312) 243,-2339 4129,-2339 C23.1
A: C5.2 D5.1 P3.1 Q6.3 R11.1 T1.3 T2.2 T3.3 T4.2 | length 992.9
  Top Layer w12: C5.2@579,-2129 603,-2129 653,-2179 Q6.3@694,-2179 ; D5.1@614.06,-1999 T4.2@614.06,-1485.06 ; Q6.3 695,-1999
  Top Layer w15: D5.1@606.06,-1999 R11.1@755.69,-1999
  other v1: 110,-1464 160,-1464 210,-1464 260,-1464 310,-1464 360,-1464 410,-1464 635,-1464 685,-1464 735,-1464 785,-1464 835,-1464 885,-1464 935,-1464 110,-1414 160,-1414 210,-1414 260,-1414 310,-1414 360,-1414 410,-1414 635,-1414 685,-1414 735,-1414 785,-1414 835,-1414 885,-1414 935,-1414 110,-1364 160,-1364 210,-1364 260,-1364 310,-1364 360,-1364 410,-1364 635,-1364 685,-1364 735,-1364 785,-1364 835,-1364 885,-1364 935,-1364 110,-1314 160,-1314 210,-1314 260,-1314 310,-1314 360,-1314 410,-1314 635,-1314 685,-1314 735,-1314 785,-1314 835,-1314 885,-1314 935,-1314 110,-1264 160,-1264 210,-1264 260,-1264 310,-1264 360,-1264 410,-1264 635,-1264 685,-1264 735,-1264 785,-1264 835,-1264 885,-1264 935,-1264
B: C6.2 D6.1 P4.1 Q7.3 R12.1 T5.3 T6.2 T7.3 T8.2 | length 979
  Top Layer w12: C6.2@1631,-2128 1667,-2128 1722,-2183 Q7.3@1755,-2183 ; T8.2@1660,-1513 1660,-1990 1819,-1990 R12.1@1822,-1987 ; Q7.3@1756,-2184 1756,-1992
  other v1: 1160,-1464 1210,-1464 1260,-1464 1310,-1464 1360,-1464 1410,-1464 1460,-1464 1685,-1464 1735,-1464 1785,-1464 1835,-1464 1885,-1464 1935,-1464 1985,-1464 1160,-1414 1210,-1414 1260,-1414 1310,-1414 1360,-1414 1410,-1414 1460,-1414 1685,-1414 1735,-1414 1785,-1414 1835,-1414 1885,-1414 1935,-1414 1985,-1414 1160,-1364 1210,-1364 1260,-1364 1310,-1364 1360,-1364 1410,-1364 1460,-1364 1685,-1364 1735,-1364 1785,-1364 1835,-1364 1885,-1364 1935,-1364 1985,-1364 1160,-1314 1210,-1314 1260,-1314 1310,-1314 1360,-1314 1410,-1314 1460,-1314 1685,-1314 1735,-1314 1785,-1314 1835,-1314 1885,-1314 1935,-1314 1985,-1314 1160,-1264 1210,-1264 1260,-1264 1310,-1264 1360,-1264 1410,-1264 1460,-1264 1685,-1264 1735,-1264 1785,-1264 1835,-1264 1885,-1264 1935,-1264 1985,-1264
BT_PWM: R17.1 U9.3 | length 384.7
  Top Layer w12: U9.3@3306,-2711 3301,-2706 3259,-2706 3247,-2694 3247,-2562 3338,-2471 R17.1@3338,-2413
C: C18.2 D8.1 P5.1 Q18.3 R35.1 T9.3 T10.2 T11.3 T12.2 | length 957.8
  Top Layer w12: C18.2@2679,-2123 2712,-2123 2780.4,-2191.4 Q18.3@2812.04,-2191.4 ; Q18.3@2816.4,-2190.36 2816.4,-1990
  Top Layer w15: D8.1@2710,-1972 T12.2@2710,-1507 ; D8.1@2736.96,-1988.6 R35.1@2868,-1988.6
  other v1: 2210,-1464 2260,-1464 2310,-1464 2360,-1464 2410,-1464 2460,-1464 2510,-1464 2710,-1464 2760,-1464 2810,-1464 2860,-1464 2910,-1464 2960,-1464 3010,-1464 2210,-1414 2260,-1414 2310,-1414 2360,-1414 2410,-1414 2460,-1414 2510,-1414 2710,-1414 2760,-1414 2810,-1414 2860,-1414 2910,-1414 2960,-1414 3010,-1414 2210,-1364 2260,-1364 2310,-1364 2360,-1364 2410,-1364 2460,-1364 2510,-1364 2710,-1364 2760,-1364 2810,-1364 2860,-1364 2910,-1364 2960,-1364 3010,-1364 2210,-1314 2260,-1314 2310,-1314 2360,-1314 2410,-1314 2460,-1314 2510,-1314 2710,-1314 2760,-1314 2810,-1314 2860,-1314 2910,-1314 2960,-1314 3010,-1314 2210,-1264 2260,-1264 2310,-1264 2360,-1264 2410,-1264 2460,-1264 2510,-1264 2710,-1264 2760,-1264 2810,-1264 2860,-1264 2910,-1264 2960,-1264 3010,-1264
CSA: C16.2 U4.1 U4.2 U5.19 | length 1007.4
  Top Layer w12: U5.19@2135,-3144 U5.19@2135.04,-3146.37 ; U5.19@2136,-3149 2136,-3309 2163,-3336 2540,-3336 2599,-3277 C16.2 ; U4.1@2731,-3149 U4.2@2781,-3149 ; C16.2@2767,-3277 C16.2@2776,-3268 ; C16.2@2779,-3268 U4.2@2779,-3165 ; U4.2@2779,-3156 U4.2
D1: R52.2 U5.13 | length 413.5
  Top Layer w12: R52.2 1637,-3011 1651.25,-2996.75 U5.13
D2: R47.2 U5.14 | length 317.6
  Top Layer w12: R47.2@1700,-3028.24 U5.14
FAN: R61.2 U5.32 | length 2648.5
  Top Layer w12: U5.32@2331.59,-2871 v7(2411,-2871) ; v7(2650,-3322) 2650,-3380 2666,-3396 4236,-3396 4341,-3291 R61.2
  Bottom Layer w12: v7(2411,-2871) 2609,-2871 2650,-2912 v7(2650,-3322)
GND: C1.2 C2.2 C4.2 C8.2 C9.1 C10.1 C11.1 C12.1 C13.1 C14.2 C15.2 C16.1 C17.1 C19.1 C20.2 C22.2 C23.2 C25.2 C26.1 C27.2 C28.2 C29.2 C30.2 C31.1 C32.2 C33.1 C34.1 C35.1 C36.2 C38.2 C39.2 C41.1 C42.1 C43.1 C44.1 C45.1 D9.2 D10.2 D11.2 D13.1 D14.2 P2.2 P6.1 P7.1 P8.3 P11.2 pad.0 pad.1 pad.2 pad.3 Q9.3 Q14.1 Q15.1 Q21.1 Q22.1 R41.2 R43.1 R46.2 R63.2 T2.3 T4.3 T6.3 T8.3 T10.3 T12.3 U1.4 U2.3 U3.4 U4.4 U5.3 U5.5 U5.21 U6.0 U6.7 U8.7 U9.1 | length 7503.3
  Top Layer w20: 2735,-3345 C17.1 ; U6.0@3857,-2077 U6.7
  Top Layer w25: 2930,-2770 2930,-2570
  Top Layer w30: 918,-413 1057,-413 ; 1011,-455 1011,-316 ; 1955,-413 2094,-413 ; 2050,-456 2050,-317 ; 3177,-420 3316,-420 ; C4.2@3268,-1725 3268,-1586 ; 3269,-469 3269,-330 ; 4040,-2710 4040,-2610 ; 4320,-2430 4420,-2430 ; 4370,-2470 4370,-2370
  Top Layer w35: 3863.08,-1852.99 4053.08,-1852.99 ; 3940,-1920 3940,-1730 ; 4290,-1850 4430,-1850 ; 4353,-1922 4353,-1732
  Top Layer w60: 4097,-1386 4317,-1386 ; 4099,-746 4319,-746 ; 4165,-1512 4165,-1292 ; 4166,-840 4166,-620
  Top Layer w70: 2973,-76 3574,-76 ; 2974,-271 3575,-271 ; 3100,-404 3100,23 ; 3489,-416 3489,11
  Bottom Layer w25: 1340,-3430 1340,-3300
  Bottom Layer w70: 2979,-271 3579,-271 ; 2992,-75 3592,-75 ; 3099,-411 3099,16 ; 3489,-417 3489,10
  other v2: 2710,-3340 3600,-3300 3625,-3300 3650,-3300 2400,-3290 2545,-3270 2400,-3265 2705,-3235 1480,-3075 1480,-3050 1365,-2975 1365,-2950 3785,-2890 1900,-2800 1925,-2800 1490,-2790 3780,-2740 3900,-2295 3925,-2295 1758,-2283 3090,-2270 3090,-2240 4010,-2155 3060,-1970 570,-1840 1600,-1840 2660,-1840 570,-1810 1600,-1810 1750,-1700 50,-1690 80,-1690 110,-1690 1750,-1670 2660,-1670 1200,-1660 2770,-1660 2800,-1660 720,-1650 1600,-1650 2660,-1640 1170,-1630 1200,-1630 1230,-1630 720,-1620 1600,-1620 2660,-1610 1200,-1600 2370,-1600 2400,-1600 2430,-1600 2900,-1600 2930,-1600 2960,-1600 3140,-1400 3240,-1400 3140,-1370 3240,-1370 3140,-1340 3240,-1340 4330,-1130 4300,-1100 4330,-1100 4360,-1100 0,-1090 4330,-1070 0,-1060 0,-1030 0,-1000 1090,-960 2100,-960 3330,-950 1060,-930 1090,-930 1120,-930 2070,-930 2100,-930 2130,-930 3030,-930 3300,-920 3330,-920 3360,-920 1090,-900 2100,-900 3000,-900 3030,-900 3060,-900 3330,-890 3030,-870 3640,-700 3640,-670 3640,-640 4350,-430 4320,-400 4350,-400 4380,-400 4350,-370 100,-290 100,-260 100,-230 3300,-230 100,-200 1000,-200 2100,-200 3270,-200 3300,-200 3330,-200 1000,-170 2100,-170 3300,-170 970,-160 1030,-160 2070,-160 2130,-160 1000,-140 2100,-140 1000,-110 2100,-110
  other v3: 320,-1865 350,-1865 380,-1865 410,-1865 840,-1865 870,-1865 900,-1865 930,-1865 1360,-1865 1390,-1865 1420,-1865 1450,-1865 1880,-1865 1910,-1865 1940,-1865 1970,-1865 2400,-1865 2430,-1865 2460,-1865 2490,-1865 2920,-1865 2950,-1865 2980,-1865 3010,-1865 320,-1835 410,-1835 840,-1835 930,-1835 1360,-1835 1450,-1835 1880,-1835 1970,-1835 2400,-1835 2490,-1835 2920,-1835 3010,-1835 320,-1805 410,-1805 840,-1805 930,-1805 1360,-1805 1450,-1805 1880,-1805 1970,-1805 2400,-1805 2490,-1805 2920,-1805 3010,-1805 320,-1775 410,-1775 840,-1775 930,-1775 1360,-1775 1450,-1775 1880,-1775 1970,-1775 2400,-1775 2490,-1775 2920,-1775 3010,-1775 320,-1745 350,-1745 380,-1745 410,-1745 840,-1745 870,-1745 900,-1745 930,-1745 1360,-1745 1390,-1745 1420,-1745 1450,-1745 1880,-1745 1910,-1745 1940,-1745 1970,-1745 2400,-1745 2430,-1745 2460,-1745 2490,-1745 2920,-1745 2950,-1745 2980,-1745 3010,-1745
  other v4: -45,-3460 110,-3460 140,-3460 170,-3460 3350,-3360 4290,-3280 4290,-3250 1840,-3080 2860,-3040 3990,-2960 490,-2880 3580,-2880 3580,-2860 1690,-2810 1710,-2810 490,-2750 -30,-2680 -30,-2650 490,-2650 2630,-2640 720,-2600 2770,-2600 2790,-2600 490,-2590 720,-2570 3080,-2570 3100,-2570 190,-2490 580,-2450 610,-2450 220,-2380 1050,-2290 3550,-2290 1480,-2270 2060,-2270 2080,-2270 2100,-2270 1050,-2260 2530,-2250 1050,-2230 2530,-2220 3830,-2200 3860,-2200 1480,-2130 250,-2120 404,-2120 1310,-2120 1480,-2110 2325,-2110 2346.1,-2110 1310,-2100 440,-2050 1490,-2010 1490,-1990 -40,-1940 -20,-1940 0,-1940
  other v5: 3990,-3200 3050,-3190 3080,-3190 3110,-3190 3950,-3150 3990,-3150 4030,-3150 3430,-3100 3990,-3100 3430,-3070 3430,-3040 2960,-2900 2990,-2900 3200,-2900 3230,-2900 3780,-2650 3320,-2560 3500,-2430 3530,-2430 3560,-2430 3360,-2160 3390,-2160 3500,-2160 3590,-2150 3670,-2140 3310,-1960 3310,-1940 3560,-1850 3800,-1700 3830,-1700 3800,-1670 3830,-1670 3260,-1620 3290,-1620 3430,-1610 3460,-1610 3430,-1580 3460,-1580
  other v6: 690,-3460 720,-3460 1290,-3460 1320,-3460 3810,-3460 3830,-3460 3980,-3460 4010,-3460 2360,-3400 2390,-3400 2420,-3400 840,-3370 870,-3370 1200,-3360 840,-3340 870,-3340 1200,-3330 2040,-3290 1830,-3280 1940,-3260 1830,-3250 1330,-3230 1940,-3230 1330,-3200 700,-3160 700,-3130 700,-3100 2270,-3020 50,-3010 80,-3010 2183,-2980 2360,-2810 2360,-2780 2170,-2720 2200,-2720 2230,-2720
HA: U5.25 U8.12 | length 1375.1
  Top Layer w10: U8.12@1106,-2866 1192,-2866 1441,-3115 v7(1505,-3115) ; v7(2355,-3115) U5.25@2355,-3092
  Bottom Layer w10: v7(1505,-3115) v7(2355,-3115)
HB: U5.24 U8.10 | length 1317.8
  Top Layer w10: U8.10@1117,-2966 1221,-2966 1404,-3149 v7@1497,-3149 ; U5.24@2295,-3150 v7@2327,-3150
  Bottom Layer w10: v7(1496,-3150) v7(2326,-3150)
HC: U5.23 U8.8 | length 1248.2
  Top Layer w10: U8.8@1103,-3068 1256,-3068 1378,-3190 v7(1495,-3190) ; v7@2261.74,-3189.74 v7(2262,-3190) 2261.74,-3190 U5.23@2261.74,-3152
  Bottom Layer w10: v7(1495,-3190) v7(2262,-3190)
M8_DOG: U2.6 U5.11 | length 430.2
  Top Layer w12: U2.6 1713,-2852 1794,-2933 U5.11@2020,-2933
M8_RST: P1.1 U2.7 U5.29 | length 1554.3
  Top Layer w10: U5.29@2345,-2965 U5.29@2348.36,-2965.02
  Top Layer w12: v7(1504,-3004) 1504,-2838 1540,-2802 U2.7 ; P1.1@1722.5,-3362.5 1777,-3308 1777,-3088 v7@1806.78,-3058.22 ; v7(2191,-3031) 2257,-2965 U5.29@2349,-2965
  Bottom Layer w12: v7(1504,-3004) 1531,-3031 v7(2191,-3031) ; v7(1807.56,-3059) 1807.56,-3031
MISO: P1.3 U5.16 | length 310.8
  Top Layer w12: P1.3@1919,-3359 1925,-3359 2011,-3273 U5.16@2011,-3089.81
NetC3_1: C3.1 D1.2 D2.1 | length 206
  Top Layer w30: C3.1@3490,-1944 D1.2@3490,-1738
NetC3_2: C3.2 Q3.1 Q9.1 | length 251.9
  Top Layer w20: Q9.1 C3.2@3390.64,-1931.6 ; Q9.1@3396.69,-2034.6 Q3.1
NetC5_1: C5.1 D5.2 Q6.1 R5.2 T1.1 T3.1 | length 2216.2
  Top Layer w12: T1.1 165,-984 195,-954 655,-954 685,-984 T3.1 ; R5.2@487.6,-2201 D5.2@487.6,-1983 ; 487.6,-2053 637,-2053 657.6,-2073.6 Q6.1 ; D5.2@514,-1994 514,-954
NetC6_1: C6.1 D6.2 Q7.1 R6.2 T5.1 T7.1 | length 2171.1
  Top Layer w12: T5.1@1206,-1089 1205.93,-1085.52 1205,-1041 1205,-985 1231,-959 1697,-959 1725,-987 T7.1@1725,-1082 ; R6.2@1547,-2177 1547,-962 ; R6.2@1548,-2191 R6.2@1547.98,-2189 ; 1550,-2054 1707,-2054 1717.6,-2064.6 Q7.1
NetC9_2: C9.2 Q14.3 R18.2 R20.2 R27.2 | length 304.9
  Top Layer w12: C9.2@315,-2054 335,-2074 Q14.3@335,-2104
  Top Layer w15: R20.2@128.36,-2036 R27.2@375,-2036
NetC11_2: C11.2 Q15.3 R19.2 R21.2 R28.2 | length 313.5
  Top Layer w12: C11.2@1363,-2051 1385,-2073 Q15.3@1385,-2109
  Top Layer w15: R21.2@1173.64,-2034 R28.2@1420,-2034
NetC17_2: C17.2 R31.1 U4.3 | length 158
  Top Layer w12: 2831,-3257 U4.3@2831,-3166
  Top Layer w15: C17.2@2828,-3277 R31.1
NetC18_1: C18.1 D8.2 Q18.1 R33.2 T9.1 T11.1 | length 2228.9
  Top Layer w12: 2604,-2052 2762,-2052 2776,-2066 Q18.1@2776,-2095
  Top Layer w15: T9.1@2244,-1091 2244.11,-1085.52 2245,-1041 2245,-962 2268,-939 2730,-939 2765,-974 T11.1@2765,-1086 ; R33.2@2603,-2179 2603,-941.96
NetC19_2: C19.2 Q21.3 R38.2 R39.2 R45.2 | length 308.2
  Top Layer w12: C19.2@2397,-2056 2415,-2074 Q21.3@2415,-2110.4
  Top Layer w15: R39.2@2208.64,-2034 R45.2@2455,-2034
NetC20_1: C20.1 U5.7 Y1.2 | length 446.1
  Top Layer w12: U5.7@2104,-2813 2104,-2665 2126,-2643 C20.1@2393,-2643
NetC22_1: C22.1 U5.8 Y1.1 | length 353.7
  Top Layer w12: C22.1@1869,-2643 2033,-2643 2071.76,-2681.76 U5.8@2071.76,-2816.65
NetC24_1: C24.1 D13.2 L1.1 U6.8 | length 40
  Top Layer w18: C24.1@3894,-1966 3934,-1966
NetC24_2: C24.2 U6.1 | length 117.8
  Top Layer w12: U6.1@3750,-2020 3750,-1971 3764,-1957 C24.2
NetC25_1: C25.1 U5.20 | length 114
  Top Layer w12: C25.1@2168,-3261 U5.20@2168,-3147
NetC30_1: C30.1 R44.1 U6.6 | length 164.4
  Top Layer w12: U6.6 3994,-2127 4027,-2094 R44.1@4108,-2094
NetC31_2: C31.2 R44.2 | length 81
  Top Layer w12: C31.2@4117,-2225 R44.2@4117,-2144
NetC33_2: C33.2 R56.1 U8.5 | length 356.7
  Top Layer w15: C33.2@613,-3036 613,-2981 764,-2981 782,-2963 901.54,-2963 U8.5@905.54,-2967
NetC34_2: C34.2 R57.1 U8.3 | length 382.2
  Top Layer w15: R57.1@612,-2816 C34.2@612,-2749 ; R57.1 721,-2810 778,-2867 U8.3@905.54,-2867
NetC35_2: C35.2 R58.1 U8.1 | length 399.9
  Top Layer w15: R58.1@613,-2645 711,-2645 830,-2764 891,-2764 U8.1@895,-2768 ; R58.1@615,-2655 C35.2@615,-2588
NetC38_1: C38.1 U9.5 | length 111
  Top Layer w12: U9.5@3532,-2762 C38.1@3643,-2762
NetC39_1: C39.1 R60.1 U9.2 U9.6 | length 460.7
  Top Layer w12: U9.2@3319.06,-2661 3324.06,-2656 3399,-2656 3449,-2706 C39.1@3644,-2706 ; 3386,-2655 R60.1@3386,-2542
NetC43_2: C43.2 R62.1 R63.1 U4.5 | length 273
  Top Layer w15: U4.5@2885,-2964 R62.1@3056,-2964 ; R63.1 R62.1@3064.6,-2945
NetD3_1: D3.1 Q1.3 Q6.2 R11.2 | length 479.6
  Top Layer w12: Q6.2@733,-2096 907,-2096 918,-2107 Q1.3@918,-2282 ; D3.1@826,-2104 R11.2@826,-1989
NetD3_2: D3.2 R5.1 | length 312.3
  Top Layer w12: R5.1 562.4,-2228.4 574,-2240 798,-2240 D3.2@821,-2217
NetD4_1: D4.1 Q2.3 Q7.2 R12.2 | length 421.4
  Top Layer w15: Q7.2@1797,-2097 1967,-2097 1980,-2110 Q2.3@1980,-2289 ; D4.1@1887,-2059 R12.2@1887,-2005
NetD4_2: D4.2 R6.1 | length 305
  Top Layer w12: R6.1@1622.4,-2200 1622.4,-2230.4 1635,-2243 1855,-2243 D4.2@1881,-2217
NetD7_1: D7.1 Q16.3 Q18.2 R35.2 | length 436
  Top Layer w15: Q18.2@2851.96,-2096.6 3018.6,-2096.6 3032,-2110 Q16.3@3032,-2298 ; D7.1@2947.6,-2067.04 R35.2@2947.6,-2004.64
NetD7_2: D7.2 R33.1 | length 331.6
  Top Layer w12: R33.1@2673.6,-2182.64 2673.6,-2236.6 2683,-2246 2912,-2246 D7.2@2937,-2221
NetD9_1: D9.1 F1.2 U6.2 | length 470.6
  Top Layer w40: 3678,-2072 3683,-2077 U6.2
  Top Layer w60: F1.2@3622,-1698.85 3622,-2022 3672,-2072 3678,-2072
NetD10_1: D10.1 R49.1 | length 68
  Top Layer w12: R49.1 D10.1@3643,-2859
NetD11_1: D11.1 R52.1 | length 66
  Top Layer w12: D11.1@1637,-3172 R52.1
NetD12_1: D12.1 P9.2 Q22.3
NetD14_1: D14.1 R47.1 | length 66
  Top Layer w12: D14.1@1697,-3174.83 R47.1@1697,-3108.83
NetP7_4: P7.4 R55.1 R58.2 | length 285
  Top Layer w15: P7.4@329,-2693 R55.1@547,-2693 ; R55.1@545,-2710 R58.2@545,-2643
NetP7_5: P7.5 R54.1 R57.2 | length 295
  Top Layer w15: P7.5@323,-2812 R57.2@551,-2812 ; R54.1@544,-2867 R57.2@544,-2800
NetP7_6: P7.6 R53.1 R56.2 | length 285
  Top Layer w15: P7.6@316,-2929 R53.1@534,-2929 ; R56.2@544,-2979 R53.1@544,-2912
NetQ1_2: Q1.2 Q4.3 R1.1 | length 240.3
  Top Layer w12: Q4.3@715.36,-2338 752,-2338 780,-2310 867,-2310 877.6,-2320.6 Q1.2
NetQ2_2: Q2.2 Q5.3 R2.1 | length 246.3
  Top Layer w12: Q5.3@1783.5,-2337.04 Q5.3@1784,-2337 ; Q5.3@1787,-2342.4 1787,-2316 1798,-2305 1924,-2305 1943,-2324 Q2.2@1943,-2375
NetQ3_2: Q3.2 Q8.3 Q9.2 R7.1 | length 482.9
  Top Layer w15: R7.1@3307,-2218 3307,-2123 3320.6,-2109.4 Q3.2 ; Q8.3@3550,-2253 Q3.2@3550,-2109.4
NetQ4_1: Q4.1 R13.2 | length 69
  Top Layer w12: R13.2@562.36,-2376 Q4.1@631.36,-2376
NetQ4_2: Q4.2 R8.1 | length 78
  Top Layer w12: R8.1@553.36,-2301 Q4.2@631.36,-2301
NetQ5_1: Q5.1 R14.2 | length 51
  Top Layer w12: R14.2@1637,-2377 Q5.1@1688,-2377
NetQ5_2: Q5.2 R9.1 | length 51
  Top Layer w12: R9.1@1637,-2301 Q5.2@1688,-2301
NetQ8_1: Q8.1 R17.2 | length 158.2
  Top Layer w12: R17.2@3414,-2416 3447,-2416 3462,-2401 Q8.1@3462,-2297
NetQ8_2: Q8.2 R10.1 | length 79.9
  Top Layer w20: R10.1 Q8.2@3466.94,-2214.6
NetQ10_2: Q10.2 Q12.3 R15.2 | length 164.7
  Top Layer w12: Q10.2@138,-2192.6 138,-2325 146,-2333 Q12.3@167,-2333
NetQ10_3: Q10.3 R20.1 | length 298.7
  Top Layer w12: R20.1@135,-1959 134.83,-1959.01 134.84,-1961.6 134.86,-1963.86 130.1,-1959.1 89.9,-1959.1 80,-1969 80,-2099 90,-2109 175,-2109 Q10.3
NetQ11_2: Q11.2 Q13.3 R16.2 | length 167.5
  Top Layer w12: Q11.2 1187.6,-2321.6 1200,-2334 Q13.3@1221,-2334
NetQ11_3: Q11.3 R21.1 | length 286.9
  Top Layer w12: R21.1 1137.4,-1961.6 1125,-1974 1125,-2089 1141.36,-2105.36 Q11.3
NetQ12_1: Q12.1 R22.2 | length 162.6
  Top Layer w12: Q12.1@215,-2433 287,-2433 299.6,-2420.4 R22.2@299.6,-2347.64
NetQ13_1: Q13.1 R23.2 | length 157.4
  Top Layer w12: Q13.1@1267,-2433 1333,-2433 1347.6,-2418.4 R23.2@1347.6,-2347.64
NetQ14_2: Q14.2 R25.1 | length 62.4
  Top Layer w12: R25.1@297.6,-2255.04 Q14.2
NetQ15_2: Q15.2 R26.1 | length 62.4
  Top Layer w12: R26.1@1347.6,-2255.04 Q15.2
NetQ16_2: Q16.2 Q17.3 R32.1 | length 247.3
  Top Layer w12: Q17.3@2842,-2339 2842,-2311 2852.4,-2300.6 2974.6,-2300.6 2989,-2315 Q16.2@2989,-2377
NetQ17_1: Q17.1 R36.2 | length 62.4
  Top Layer w15: R36.2@2677.96,-2376.6 Q17.1@2740.36,-2376.6
NetQ17_2: Q17.2 R34.1 | length 62.4
  Top Layer w15: R34.1@2683.96,-2301.6 Q17.2@2746.36,-2301.6
NetQ19_2: Q19.2 Q20.3 R37.2 | length 165.4
  Top Layer w12: Q19.2 2217.6,-2326.6 2225,-2334 Q20.3@2246,-2334
NetQ19_3: Q19.3 R39.1 | length 284
  Top Layer w12: R39.1 2167.4,-1961.6 2155,-1974 2155,-2084 2176.36,-2105.36 Q19.3
NetQ20_1: Q20.1 R40.2 | length 156.8
  Top Layer w12: Q20.1@2296,-2432 2362,-2432 2377.6,-2416.4 R40.2@2377.6,-2347.64
NetQ21_2: Q21.2 R42.1 | length 62.4
  Top Layer w12: R42.1@2377.6,-2255.04 Q21.2
NetQ22_2: Q22.2 R61.1 | length 79.4
  Top Layer w12: R61.1@4270,-3190 Q22.2@4270,-3110.64
NetR18_1: R18.1 T2.1 | length 170.7
  Top Layer w12: T2.1@165,-1809 165,-1859 215,-1909 R18.1@215,-1959
NetR19_1: R19.1 T6.1 | length 149
  Top Layer w12: T6.1@1207,-1832 1207,-1866 1265,-1924 R19.1@1265,-1957
NetR24_1: R24.1 U2.4 | length 89.6
  Top Layer w12: R24.1@1319,-2899 U2.4@1408.64,-2899
NetR27_1: R27.1 T4.1 | length 430
  Top Layer w12: R27.1@395,-1949 v7(425,-1949) ; v7(685,-1949) T4.1@685,-1809
  Bottom Layer w12: v7(425,-1949) v7(685,-1949)
NetR28_1: R28.1 T8.1 | length 415.7
  Top Layer w12: R28.1@1430,-1961.6 1438.6,-1953 1469,-1953 1480,-1942 v8@1480,-1940 ; T8.1@1724,-1800 T8.1@1724.11,-1805.55 ; v8(1734,-1935) T8.1@1734,-1833
  Bottom Layer w12: v8@1485,-1936 v8@1733,-1936
  other v8: 1483,-1937
NetR30_1: R30.1 R43.2 U6.5 | length 165.6
  Top Layer w12: R43.2 R30.1 3898,-2222 U6.5@3943,-2177
NetR31_2: R31.2 U3.5 | length 682.2
  Top Layer w12: R31.2@2901,-3350 3297,-3350 3452,-3195 U3.5@3519,-3195
NetR38_1: R38.1 T10.1 | length 177.5
  Top Layer w12: T10.1@2246.4,-1799.96 2246.4,-1868.4 2279,-1901 R38.1@2279,-1964
NetR41_1: R41.1 U6.4 | length 258.3
  Top Layer w12: R41.1 3702,-2307 3678,-2283 3678,-2190 3691,-2177 U6.4@3753,-2177
NetR45_1: R45.1 T12.1 | length 442.1
  Top Layer w12: R45.1@2451.64,-1962.4 v8@2514.04,-1962.4 ; v8(2773,-1928) T12.1@2773,-1820.6
  Bottom Layer w12: v8@2513,-1961 2545,-1929 v8@2772,-1929
  other v8: 2513,-1962
NetR59_1: R59.1 R60.2 U9.7 | length 297
  Top Layer w12: R60.2@3453,-2536 3453,-2639 3470,-2656 R59.1@3640,-2656
NetU2_1: U2.1 U2.8 | length 186.6
  Top Layer w12: U2.1@1431.36,-2751 U2.8@1618,-2751
NetU8_2: U8.2 U8.13 | length 127.5
  Top Layer w15: U8.2@939,-2818 U8.13@1066.54,-2818
NetU8_4: U8.4 U8.11 | length 127.5
  Top Layer w15: U8.4@940,-2916 U8.11@1067.54,-2916
NetU8_6: U8.6 U8.9 | length 127.5
  Top Layer w15: U8.6@942,-3016 U8.9@1069.54,-3016
QEA: P2.4 R4.2 U5.1 | length 2245.6
  Top Layer w12: P2.4 330,-3345 400,-3275 1190,-3275 v7(1274,-3191) ; v2@2280,-2935 2293.24,-2921.76 U5.1
  Bottom Layer w12: v7(1274,-3191) 1530,-2935 v2(2279,-2935)
QEB: P2.3 R3.2 U5.2 | length 2130.6
  Top Layer w12: P2.3 1187.11,-3226.89 v7(1257.1,-3156.9) ; v2(2243,-2906) 2261,-2888 U5.2@2261,-2832 ; U5.2@2262,-2817 U5.2@2261.99,-2815.64
  Bottom Layer w12: v7(1257.1,-3156.9) 1508,-2906 v2(2243,-2906)
SCK: P1.4 U5.17 | length 220.1
  Top Layer w12: P1.4@2020.5,-3360.5 2074,-3307 U5.17@2074,-3162.59
SIG: P8.1 R46.1 U5.12 | length 845.6
  Top Layer w12: P8.1 1542,-3011 1587.75,-2965.25 U5.12
STEUER_A+: R13.1 U5.30 | length 2539
  Top Layer w12: R13.1 487.6,-2478.6 503,-2494 962,-2494 1036,-2568 v11(1389,-2568) ; v11(1465,-2568) 2428,-2568 2452,-2592 2452,-2917 2435,-2934 U5.30@2354,-2934
  Bottom Layer w12: v11@1390,-2568 v11@1464,-2568
STEUER_A-: R22.1 R25.2 U5.10 | length 2167.7
  Top Layer w12: R25.2 372.4,-2499.4 393,-2520 930,-2520 1044,-2634 1750,-2634 1775,-2659 1775,-2858 1820,-2903 U5.10@2026,-2903
STEUER_B+: R14.1 U5.28 | length 1632.7
  Top Layer w12: R14.1@1548,-2382 1548,-2522 1566,-2540 2444,-2540 2477,-2573 2477,-2980 2460.25,-2996.75 U5.28
STEUER_B-: R23.1 R26.2 U5.9 | length 1137.7
  Top Layer w12: R26.2 1422.4,-2586.4 1439,-2603 1770,-2603 1801,-2634 1801,-2831 1841,-2871 2008,-2871 U5.9@2009,-2870
STEUER_C+: R36.1 U5.27 | length 878.5
  Top Layer w12: U5.27 2560.76,-3028.24 2592,-2997 2592,-2385 R36.1@2599,-2378
STEUER_C-: P1.2 R40.1 R42.2 U5.15 | length 1753.6
  Top Layer w12: P1.2@1821,-3362 1877,-3306 1877,-3085 1902.26,-3059.74 v7@2084,-3059.74 ; R42.2@2441,-2268 2441,-2463 2517,-2539 v7(2517,-2996)
  Bottom Layer w12: v7(2084,-3060) 2482,-3060 2517,-3025 v7(2517,-2996)
TEMP: P11.1 R48.1 U5.26 | length 827
  Top Layer w12: U5.26@2356,-3060 2588,-3060 2637,-3011 2637,-2701 2658,-2680 P11.1@2844,-2680
VCC: C13.2 C15.1 C28.1 C29.1 D1.1 F1.1 P10.1 R29.2 R62.2 U3.1 U3.2 | length 2111
  Top Layer w15: R62.2@3148,-2957 v2(3148,-1529)
  Top Layer w20: R62.2@3148,-2957 C15.1@3314,-2957 ; U3.2@3326,-3089 C15.1@3326,-2945
  Top Layer w30: D1.1@3371,-1741 3371,-1525
  Bottom Layer w15: v2@3148,-1528 v14(3305,-1528)
VH: C4.1 D2.2 Q1.1 Q2.1 Q16.1 R1.2 R2.2 R32.2 | length 3794.6
  Top Layer w18: R1.2@800,-2387 800,-2422 818,-2440 v8(952,-2440) ; v8@952,-2441 952.4,-2441 Q1.1@952.4,-2389 ; R2.2@1872,-2376.4 1872,-2425 1889,-2442 1993,-2442 2018,-2417 2018,-2383.6 Q2.1@2017.4,-2383 ; R32.2@2916,-2375 2916,-2427 2931,-2442 3044,-2442 3068,-2418 3068,-2385.24 Q16.1@3069,-2384.24
  Top Layer w25: v15@3240,-2409 3240,-1940 3267.71,-1912.29 C4.1@3267.71,-1838
  Top Layer w30: C4.1@3277,-1839 D2.2@3380,-1839
  Bottom Layer w15: 2017,-2445 v8@2017,-2415 ; 3068,-2443 v8@3068,-2413
  Bottom Layer w25: v8@951,-2440 3211,-2440 v15@3240.5,-2410.5
  other v8: 2017,-2418 3068,-2416
  other v15: 3240,-2410
VP: C1.1 C2.1 C14.1 R29.1 T1.2 T3.2 T5.2 T7.2 T9.2 T11.2 U3.8 | length 2928.7
  Top Layer w15: 3163.77,-738.23 3190,-764.46 3190,-2790 3246,-2846 3500,-2846 3533,-2879 U3.8@3533,-3045
  Top Layer w30: T5.2@1128.12,-501.12 C1.1@1128.12,-406 ; T9.2@2160.12,-501.12 C2.1@2160.12,-406 ; 3383,-558 C14.1@3383,-428
VSA: C42.2 U4.6 U4.7 U5.22 | length 768.3
  Top Layer w12: U5.22@2229,-3157.61 2229,-3210 2242,-3223 2530,-3223 2686,-3067 2759,-3067 2778,-3048 U4.7@2778,-2959
pads on no net: P7.2 U2.5 U3.3 U3.6 U3.7 U5.31 U6.3

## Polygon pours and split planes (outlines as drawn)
GND on Top Layer "Bottom Layer-No Net" (solid, remove dead copper, pour order 1006): -480,220 -470,210 4750,210 4750,-1900 -220,-1900
GND on Top Layer "Bottom Layer-No Net" (solid, remove dead copper, pour order 1007): -193,-1897 685,-1897 4527,-1897 4597,-1967 4567,-1997 4567,-3637 -173,-3637 -203,-3607
GND on Top Layer "Bottom Layer-No Net" (solid, remove dead copper, pour order 1008): 2530,-1740 3160,-1740 3200,-1780 3220,-1800 3220,-2390 2640,-2390 2610,-2420
NetD12_1 on Top Layer "Bottom Layer-No Net" (solid, remove dead copper, pour order 1009): 4333,-2879 4404,-2879 4403,-2880 4403,-3044 4283,-3044 4282,-3045 4284,-3043 4284,-2986 4314,-2986 4315,-2985 4327,-2973 4327,-2879
GND on Bottom Layer "Bottom Layer-No Net" (solid, remove dead copper, pour order 1010): -373,193 -343,223 4742,223 4742,-1912 4737,-1907 -168,-1907
GND on Bottom Layer "Bottom Layer-No Net" (solid, remove dead copper, pour order 1011): -153,-1887 4537,-1887 4587,-1937 4537,-1987 4537,-3617 -143,-3617

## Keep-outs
Keep-Out Layer:
  lines w7.87: -95,-3462 -95,46 ; -57,-3502 4442,-3502 ; -57,86 4438,86 ; 4474.33,-3469 4474.33,49.67
  lines w8: -95,-3462 ccw(c-55,-3462) -55,-3502 ; -95,46 cw(c-55,46) -55,86 ; 4438,86 cw(c4438,49.67) 4474.33,49.67 ; 4440,-3502 ccw(c4440,-3467.67) 4474.33,-3467.67

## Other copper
Top Layer:
  rectangle net GND: 1766,-1917 1826,-1868
  rectangle net GND: 1021,-1929 1108,-1831
  rectangle net GND: 3945,-3040 4020,-2960
  rectangle net GND: 3835,-3175 4130,-3115
  rectangle net GND: 3930,-3360 4030,-3185
  rectangle net GND: 4300,-3485 4460,-3370
  rectangle net GND: 4330,-3475 4460,-3340
  rectangle net GND: 510,-3380 530,-3365
  rectangle net GND: 515,-3485 635,-3465
  rectangle net GND: 530,-3375 625,-3340
  rectangle net GND: 635,-3455 665,-3375
  rectangle net GND: 500,-3470 560,-3370
  rectangle net GND: 520,-3475 650,-3350
  rectangle net VP: 139,-805 3592,-503
  rectangle net VCC: 3288,-1543 4026,-1031
  rectangle net VCC: 3688,-1543 4049,-279
  rectangle net C: 2855,-1365 3072,-991
  rectangle net C: 2335,-1389 2552,-992
  rectangle net B: 1815,-1389 2032,-992
  rectangle net B: 1293,-1388 1510,-991
  rectangle net A: 772,-1390 989,-993
  rectangle net A: 255,-1387 472,-990
  region net VSA: 2772,-2937 2772,-2961 2830,-2961 2830,-2937
  rectangle net VCC: 3675,-421 4210,-1
  rectangle net NetD9_1: 3622,-1917 3823,-1791.98
  rectangle net NetC24_1: 3925,-2046 4402,-1956
  rectangle net NetC24_1: 4137,-2020 4253,-1802
  rectangle net +12V: 4175,-2963.26 4283,-2175
  rectangle net +12V: 4039,-2959 4292,-2815
  rectangle net +5V: 3845,-2918 3980,-2633
  rectangle net NetD12_1: 4322,-2943 4406,-2697
  pour cut-out: 4289.42,-1787 4289.42,-1915 4288.42,-1916 4289.42,-1917 4411.42,-1917 4411.42,-1789 4409.42,-1787
  pour cut-out: 3880,-1780 3880,-1908 3879,-1909 3880,-1910 4002,-1910 4002,-1782 4000,-1780
  pour cut-out: 3227,-377 3317,-377 3317,-467 3227,-467
  pour cut-out: 2007,-367 2097,-367 2097,-457 2007,-457
  pour cut-out: 967,-367 1057,-367 1057,-457 967,-457
  pour cut-out: 3194.71,-1652.88 3194.71,-1802.88 3344.71,-1802.88 3344.71,-1652.88
  pour cut-out: 3027,-2 3027,-152 3177,-152 3177,-2
  pour cut-out: 3417,-2 3417,-152 3567,-152 3567,-2
  pour cut-out: 3417,-197 3417,-347 3567,-347 3567,-197
  pour cut-out: 3027,-197 3027,-347 3177,-347 3177,-197
  pour cut-out: 4220,-799 4220,-700 4213,-693 4112,-693 4112,-793 4106,-799
  pour cut-out: 4217,-1437 4217,-1332 4112,-1332 4112,-1437
Bottom Layer:
  rectangle net GND: 3479,-1828 3748,-1385
  rectangle net GND: 3302,-1253 3593,-1023
  rectangle net GND: 3363,-862 3516,-620
  rectangle net GND: 4295,-3485 4460,-3325
  rectangle net GND: 465,-3485 700,-3300
  rectangle net A: 195,-1429 845,10
  rectangle net B: 1235,-1459 1885,9
  rectangle net C: 2275,-1489 2915,9
  rectangle net C: 2155,-1519 3065,-1209
  rectangle net B: 1105,-1519 2015,-1209
  rectangle net A: 65,-1519 975,-1209
  rectangle net +5V: 1170,-2514 1206,-2479
  pour cut-out: 3563,-2 3563,-152 3413,-152 3413,-2
  pour cut-out: 3563,-197 3563,-347 3413,-347 3413,-197
  pour cut-out: 3173,-197 3173,-347 3023,-347 3023,-197
  pour cut-out: 3173,-2 3173,-152 3023,-152 3023,-2
  pour cut-out: 4113,-797 4113,-692 4218,-692 4218,-797
  pour cut-out: 4113,-1437 4113,-1332 4218,-1332 4218,-1437

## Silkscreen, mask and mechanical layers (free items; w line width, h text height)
Top Overlay:
  lines w6: 455,-2080 455,-2070 595,-2070 595,-2075 595,-2415 455,-2415 ; 455,-2075 455,-2415 ; 510,-2415 510,-2600 400,-2600 400,-2415 455,-2415 ; 1157,-3374 1157,-3378.27 ccw(c1187.73,-3378.27) 1166,-3400 ccw(c1180.49,-3385.51) 1180.49,-3406 1256,-3406 ; 1242,-3420 1256,-3406 ; 1242,-3392 1256,-3406 ; 3715,-2210 3715,-2435 3865,-2435 3865,-2210 ; -85,-2070 410,-2070 420,-2070 420,-1925 -85,-1925 -85,-2070 ; 1003,-3374 1158,-3374 1158,-3306 1003,-3306 1003,-3374 ; 2560,-2625 2705,-2625 2705,-2070 2560,-2070 2560,-2625
  lines w7.87: 1515,-2620 1515,-2076 1515,-2071 1655,-2071 1655,-2076 1655,-2620
  lines w8: 1515,-2620 1655,-2620
  text "GND" at 3220,20 h78.74
  text "+48V" at 3880,20 h78.74
  text "A" at 105,-140 h160
  text "B" at 1140,-140 h160
  text "C" at 2180,-140 h160
  text "S" at 1104,-3359 h60
  text "-" at 1014,-3362 h100
  text "+" at 1052,-3364 h80
  text "OOP V1.2" at 3790,-3458 h100
  text "RS" at 1690,-3470 h60
  text "MO" at 1785,-3470 h60
  text "MI" at 1900,-3470 h60
  text "CK" at 1995,-3470 h60
Top Solder:
  rectangle: 2840,-1271 3090,-981
  rectangle: 2320,-1331 2558,-981
  rectangle: 1810,-1281 2040,-981
  rectangle: 1290,-1321 1520,-981
  rectangle: 760,-1271 1000,-981
  rectangle: 250,-1271 480,-981
  rectangle: 300,-1880 440,-1740
  rectangle: 820,-1880 960,-1740
  rectangle: 1340,-1880 1480,-1740
  rectangle: 1860,-1880 2000,-1740
  rectangle: 2380,-1880 2520,-1740
  rectangle: 2900,-1880 3040,-1740
  lines w40: 3869.72,-36.08 cw(c3874.08,-36.08) 3871,-33 ; 4128.59,-173 cw(c4128.59,-176.41) 4131,-174
  lines w50: 180,-678 cw(c208.97,-706.97) 208.97,-666
  lines w60: 116,-707 3352.03,-707 ; 3440,-1140 3760,-1140 ; 3753,-173 4128.59,-173 ; 3756.68,-1140.37 ccw(c3756.68,-1036.68) 3830,-1110 ; 3834.64,-1105.36 ccw(c3749.29,-1020) 3870,-1020 ; 3869.72,-1020 3869.72,-746 3869.72,-36.08
Mechanical 15:
  circle w5.91: c229,-471.96 r62.99
  lines w6: -62.34,-471.96 229,-471.96 229,-407
  lines w9.84: -63,-2375.5 -63,-407 3267.71,-407 3267.71,-2375.5 -63,-2375.5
